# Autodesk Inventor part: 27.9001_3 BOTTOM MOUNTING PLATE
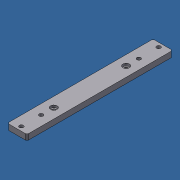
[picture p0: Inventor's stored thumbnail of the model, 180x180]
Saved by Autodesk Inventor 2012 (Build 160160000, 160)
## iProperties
Created: 2013-11
Part Number: 27.9001_3 BOTTOM MOUNTING PLATE
Material: Aluminum-6061
Description: AL BARSTOCK 1/2" x 1.75"
Document SubType Name: Modeling
Designer: Admin
Stock Number: 20.9339 AL BARSTOCK 1/2" x 1.75"
Density: 2.71 g/cm^3
Author: Admin
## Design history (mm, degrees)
sketch "Sketch1"
  geometry: L1 (-22.225, -6.35)-(22.225, -6.35); L2 (22.225, -6.35)-(22.225, 6.35); L3 (22.225, 6.35)-(-22.225, 6.35); L4 (-22.225, 6.35)-(-22.225, -6.35); 3 further points
  constraints: 8 end point, 2 midpoint, 2 parallel, 1 horizontal, 1 horizontal alignment, 1 perpendicular, 1 vertical alignment
  dimensions: "d0" = 44.45 distance of L2.end L3.end; "d1" = 12.7 distance of L3.end L1.start
extrude "Extrusion2" new body sketch "Sketch1" stored distance "d4" = 330.2; taper "d5" = 0 deg
chamfer "Chamfer2" distance "d33" = 3.175; stored, may be unused: second distance "d34" = 3.175, angle "d35" = 45 deg
sketch "Sketch7"
  geometry: L1 (0, 0)-(38.1, 0) reference; 4 further points
  constraints: 2 vertical alignment, 1 midpoint
  dimensions: "d48" = 82 distance of point (19.05, 165.1) point (19.05, 83.1); "d49" = 82 distance of point (19.05, 247.1) point (19.05, 165.1) (= d48)
hole "Hole4" sketch "Sketch7" at (19.05, 83.1), (19.05, 247.1) diameter "d50" = 9; stored, may be unused: countersink angle "d54" = 82 deg, drill point angle "d56" = 118 deg; dims "d51" = 19.05, "d52" = 15, "d53" = 5.5, "d55" = 25.4
sketch "Sketch8"
  geometry: L1 (0, 0)-(38.1, 0) reference; L2 (38.1, 330.2)-(0, 330.2) reference; 6 further points
  constraints: 4 vertical alignment, 1 midpoint
  dimensions: "d57" = 9.5 distance from line of point (19.05, 320.7) L2; "d58" = 45 distance of point (19.05, 275.7) point (19.05, 320.7); "d59" = 9.5 distance from line of point (19.05, 9.5) L1 (= d57); "d60" = 45 distance of point (19.05, 54.5) point (19.05, 9.5) (= d58)
hole "Hole5" sketch "Sketch8" at (19.05, 320.7), (19.05, 275.7), (19.05, 9.5), (19.05, 54.5) diameter "d61" = 9; stored, may be unused: countersink angle "d65" = 82 deg, drill point angle "d67" = 118 deg; dims "d62" = 19.05, "d63" = 13, "d64" = 5.5, "d66" = 25.4
sketch "Sketch9"
  geometry: C1 r 4.5 at (19.05, 275.7) reference; C2 r 4.5 at (19.05, 320.7) reference; C3 r 4.5 at (19.05, 54.5) reference; C4 r 4.5 at (19.05, 9.5) reference; C5 r 7.5 at (19.05, 320.7); C6 r 7.5 at (19.05, 275.7); C7 r 7.5 at (19.05, 54.5); C8 r 7.5 at (19.05, 9.5); 1 further point
  constraints: 4 centre point, 4 coincident, 3 equal radius
  dimensions: "d68" = 15 diameter of C5
extrude "Extrusion5" cut sketch "Sketch9" distance "d69" = 5.5; taper "d70" = 0 deg
body "Solid1"
